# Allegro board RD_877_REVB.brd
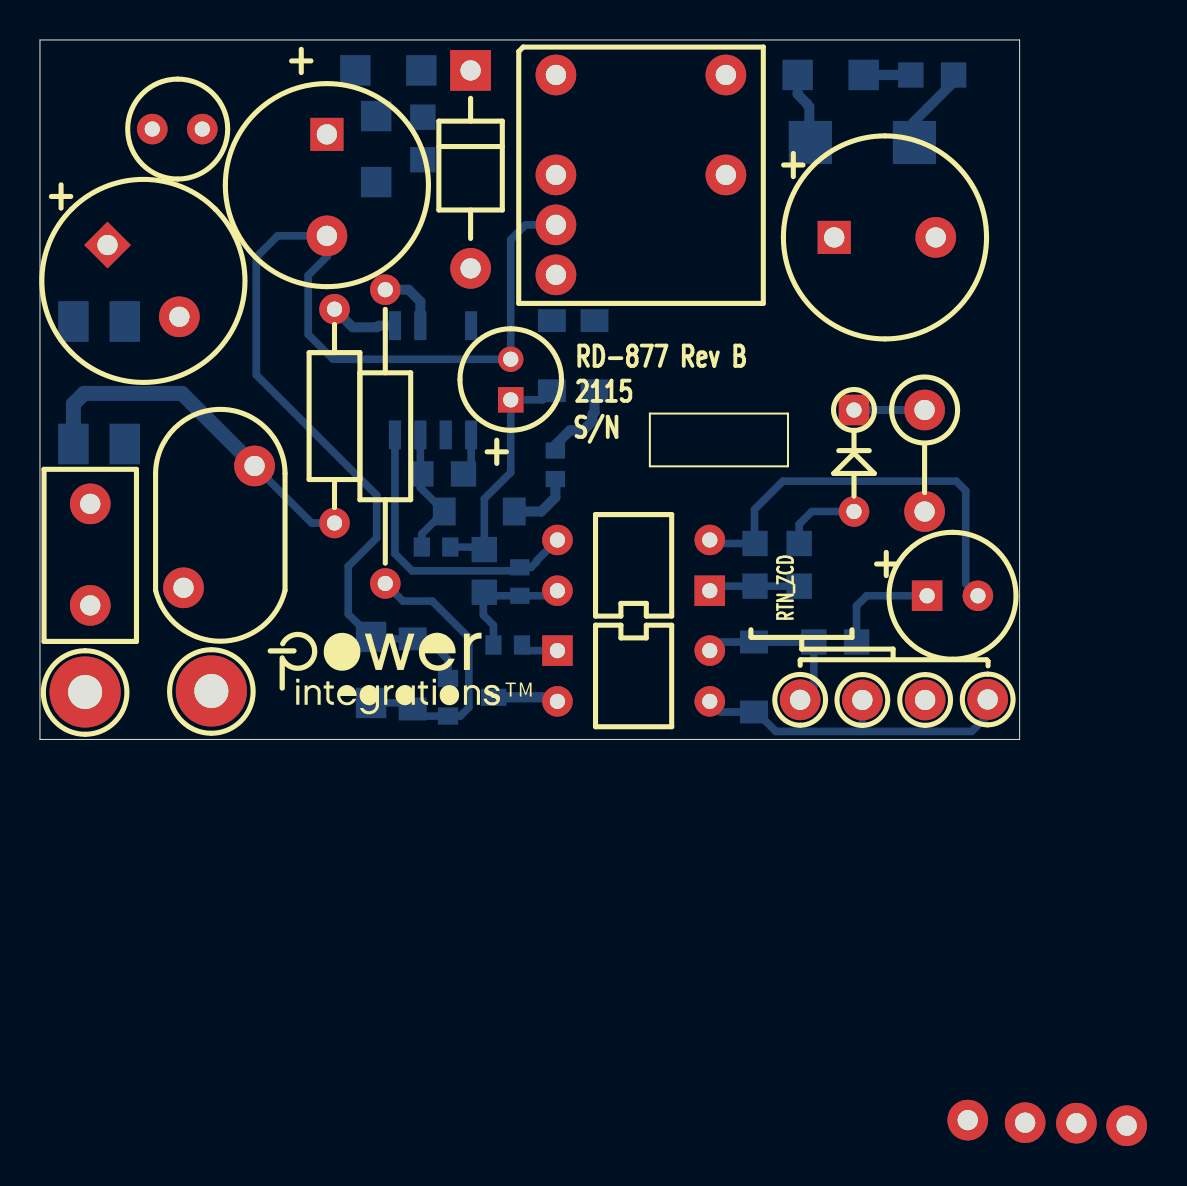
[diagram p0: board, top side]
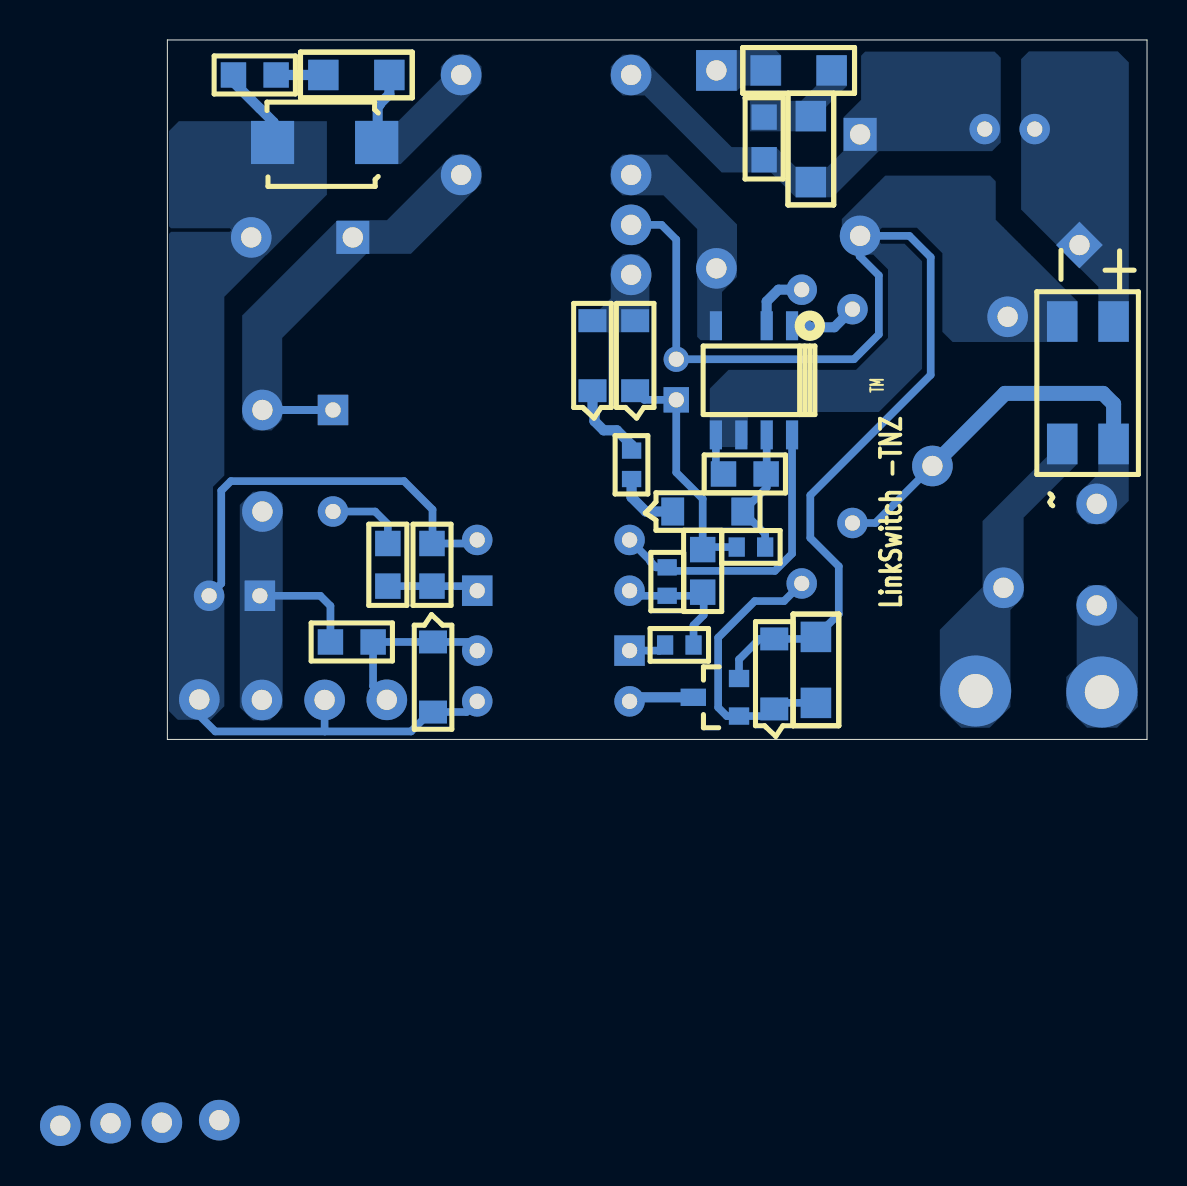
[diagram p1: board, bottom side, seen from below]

Outline 49 x 35 mm; copper layers: TOP, BOTTOM. Coordinates in mm from the lower left corner of the outline.
Outline path: 0,35 49,35 49,0 0,0 0,35

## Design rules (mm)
constraint set DEFAULT: min track width 0.508

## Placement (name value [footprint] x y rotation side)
BR1  B10S-G  [PISMSOIC4]  4.24 14.78 180 bottom
C1  6.8 uf  [PIPOLCAPCYLD400LS200040]  3.38 24.74 315 top
C2  10 uF  [PIPOLCAPCYLD400LS200040]  14.35 30.28 270 top
C3  2.2 nF  [PISMC0805]  19.15 29.01 90 bottom
C4  560 pF  [PISMC0805]  43.56 33.25 0 bottom
C5  680 uF  [PIPOLCAPCYLD400LS200040]  39.73 25.12 0 top
C6  220 uF  [PIPOLCAPCYLD250LS100030]  44.37 7.19 0 top
C7  10 uF  [PIPOLCAPCLYD200LS80030]  23.55 16.99 90 top
C8  100 nF  [PISMC0805]  19.05 13.28 0 bottom
C9  1000 pF  [PISMC0603]  24 7.19 90 bottom
D1  SS2H10-E3/52T  [PISMSMB]  38.53 29.87 0 bottom
D2  1N4007  [PIDV200X110X040DO41]  21.54 33.48 270 top
D3  1N4148W RHG  [PI_SM_SOD-123_12]  25.6 17.45 90 bottom
D4  1N4148W RHG  [PI_SM_SOD-123_12]  27.74 17.45 90 bottom
F1  1 A  [PI_RST_MICROFUSE]  2.51 6.71 90 top
L  WHT  [PITPKEYSTONE125X125]  2.26 2.37 0 top
L1  1000 uH  [PICHOKETOKINVD216H413LS098D030]  5.62 30.54 0 top
L2  Ferrite Bead  [PI12WRESD180LS675D040]  44.25 16.48 270 top
N  BLK  [PITPKEYSTONE125X125]  8.57 2.42 0 top
NOREF  -  []  -150.78 54.23 0 top
NOREF#2  -  []  -228.6 -144.78 0 top
NOREF#3  -  []  49 0 90 top
NOREF#4  -  []  0 35 0 top
NOREF#5  -  []  11.4 5.82 0 top
Q1  2N7002  [PISMSOT23123_1]  20.41 3.05 90 bottom
R2  120  [PISMR1206]  15.77 33.48 0 bottom
R3  100 k  [PISMR1206]  16.81 27.89 90 bottom
R4  100  [PISMR1206]  41.2 33.25 180 bottom
R5  392  [PISMR0805]  37.97 9.8 270 bottom
R6  2.00 k  [PISMR0805]  35.76 7.67 90 bottom
R7  24 k  [PISMR0603]  19.1 9.63 0 bottom
R8  510 k  [PI14WVRESD100LS100D030#2]  14.73 9.83 90 top
R9  240 k  [PISMR1206]  16.56 5.13 270 bottom
R10  24 k  [PISMR0603]  22.68 4.72 0 bottom
R11  100 k  [PISMR0805]  40.84 4.88 180 bottom
R13  0.0  [PISMR0805]  22.23 7.37 90 bottom
R14  510 k  [PI14WVRESD100LS100D030]  17.27 7.8 90 top
R15  2.4  [PISMR0603]  25.78 14.45 270 bottom
RTN  BLK  [PITPKEYSTONE100X100]  47.4 2 0 top
RTN_ZCD  BLK  [PITPKEYSTONE100X100]  41.13 1.97 0 top
RV1  300 Vac  [PIDISC350X225LS240X140040]  10.73 13.68 270 top
T1  EE13  [PI_BOBBIN_EE13V_10P]  25.81 33.25 270 top
U1  LNK3306  [PISMSO8_NOP3]  17.75 20.7 0 bottom
U2  PS2501-1-H-A  [PI_DIP4]  33.5 7.44 90 top
U3  LTV817D  [PI_DIP4]  25.88 4.45 270 top
UNK+12V  RED  [PITPKEYSTONE100X100]  44.27 1.97 0 top
VR2  BZX79-B11  [PIDV200X080X030DO35]  40.72 16.48 270 top
VR3  MMSZ4693T1G  [PI_SM_SOD-123_12]  18.64 1.52 90 bottom
VR4  MMSZ4689T1G  [PI_SM_SOD-123_12]  35.71 4.88 270 bottom
VR5  MMSZ5234B-7-F  [PI_SM_SOD-123_12]  23.72 11.4 180 bottom
ZCD  BLUE  [PITPKEYSTONE100X100]  38.02 1.98 0 top

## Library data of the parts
BR1 = DIODE BRIDGE_~~+-: alternate symbols: (pi_sm_soic4_slot)
C1 C6 = CAP POL
C2 C5 = CAP POL: alternate symbols: (pipolcapclyd395x630ls200030h)
C3 C4 C8 C9 = CAP NP
C7 = CAP POL: alternate symbols: (pipolcapclyd200ls80030h)
D1 = DIODE SCHOTTKY
D2 = DIODE: alternate symbols: (pidax475x125040do41,pidv200x110x040do41wbead,pidax390x125040do41)
D3 D4 = DIODE: alternate symbols: (pi_sm_sod-123_12_1)
F1 = FUSE: alternate symbols: (pirstmicrofusehoz)
L N RTN RTN_ZCD UNK+12V ZCD = TESTPOINT
L1 = INDUCTOR
L2 = INDUCTOR: alternate symbols: (pi12wvresd180ls150d040,pi12wvresd180ls200d040,pi12wvresd180ls250d040)
Q1 = FET_N_GSD
R2-R7 R9-R11 R15 = R
R8 R14 = R: alternate symbols: (pi14wvresd100ls125d030,pi14wvresd100ls150d030,pi14wvresd100ls200d030,pi14wvresd100ls300d030,pi14wresd100ls400d030,pi14wresd100ls500d030)
R13 = R: alternate symbols: (pismr0805_1)
RV1 = VARISTOR
T1 = BEE13/10PINS/GENERIC
U1 = LNK-TNZ
U2 U3 = OPTO_A_B
VR2 = DIODE_ZENER: alternate symbols: (pidax375x070030do35)
VR3-VR5 = DIODE_ZENER

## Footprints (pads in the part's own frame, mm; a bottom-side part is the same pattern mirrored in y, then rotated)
PI12WRESD180LS675D040
  round 2.032 hole 1.016: 1(0,0) 2(5.08,0)
PI14WVRESD100LS100D030
  round 1.524 hole 0.762: 1(0,0) 2(14.7,0)
PI14WVRESD100LS100D030#2
  round 1.524 hole 0.762: 1(1,0) 2(11.7,0)
PI_BOBBIN_EE13V_10P
  round 2.032 hole 1.016: 1(0,0) 2(52.299,20.599) 3(5.001,0) 4(7.501,0) 5(10,0) 6(52.578,28.55) 7(52.451,26.035) 8(5.001,8.501) 9(52.426,23.47) 10(0,8.501)
PI_DIP4
  rect 1.524x1.524 hole 0.762: 1(0,0)
  round 1.524 hole 0.762: 2(2.54,0) 3(2.54,7.62) 4(0,7.62)
PI_RST_MICROFUSE
  round 2.032 hole 1.016: 1(0,0) 2(5.08,0)
PI_SM_SOD-123_12
  rect 1.143x1.397 smd: 1(0,0) 2(3.505,0)
PICHOKETOKINVD216H413LS098D030
  round 1.524 hole 0.762: 1(0,0) 2(2.5,0)
PIDISC350X225LS240X140040
  round 2.032 hole 1.016: 1(0,0) 2(6.096,-3.556)
PIDV200X080X030DO35
  rect 1.524x1.524 hole 0.762: 1(0,0)
  round 1.524 hole 0.762: 2(5.08,0)
PIDV200X110X040DO41
  rect 2.032x2.032 hole 1.016: 1(0,0)
  round 2.032 hole 1.016: 2(9.906,0)
PIPOLCAPCLYD200LS80030
  rect 1.27x1.27 hole 0.762: 1(0,0)
  round 1.27 hole 0.762: 2(2.032,0)
PIPOLCAPCYLD250LS100030
  rect 1.524x1.524 hole 0.762: 1(0,0)
  round 1.524 hole 0.762: 2(2.54,0)
PIPOLCAPCYLD400LS200040
  rect 1.651x1.651 hole 1.016: 1(0,0)
  round 2.032 hole 1.016: 2(5.08,0)
PISMC0603
  rect 0.813x0.965 smd: 1(0,0) 2(1.422,0)
PISMC0805
  rect 1.27x1.27 smd: 1(0,0) 2(2.134,0)
PISMR0603
  rect 0.813x0.965 smd: 1(0,0) 2(1.422,0)
PISMR0805
  rect 1.27x1.27 smd: 1(0,0) 2(2.134,0)
PISMR1206
  rect 1.524x1.524 smd: 1(0,0) 2(3.302,0)
PISMSMB
  rect 2.159x2.159 smd: 1(0,0) 2(5.207,0)
PISMSO8_NOP3
  rect 0.61x1.448 smd: 1(0,0) 2(1.27,0) 4(3.81,0) 5(3.81,5.461) 6(2.54,5.461) 7(1.27,5.461) 8(0,5.461)
PISMSOIC4
  rect 1.524x2.032 smd: 1(0,0) 2(2.571,0) 3(2.571,6.129) 4(0,6.129)
PISMSOT23123_1
  rect 0.864x1.016 smd: 1(-1.88,0) 2(0,0)
  rect 0.864x1.27 smd: 3(-0.94,2.286)
PITPKEYSTONE100X100
  round 2.032 hole 1.016: 1(0,0)
PITPKEYSTONE125X125
  round 3.556 hole 1.702: 1(0,0)

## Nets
BIAS: D3.2 D4.2 T1.5
BP: C8.1 R7.1 U1.7 VR5.2
N4253666: C4.1 R4.1
N4253670: C4.2 C5.2 C6.2 D1.2 R6.2 RTN.1 RTN_ZCD.1 U2.2 U3.3(E) VR4.2
N4254079: BR1.4 C1.2 C2.2 C7.2 C8.2 Q1.2(S) R9.1 T1.4 U1.5 U1.6 VR3.2
N4254091: C7.1 D3.1 R7.2 R13.2
N4254098: C2.1 C3.1 L1.2 R3.1 T1.1
N4254129: C3.2 R2.1 R3.2
N4254146: D2.1 R2.2
N4254163: D2.2 T1.3 U1.4
N4254668: C9.2 U1.8 U2.3(E)
N4254798: R5.1 VR2.2
N4254829: R5.2 R6.1 U2.1
N4255085: BR1.3 C1.1 L1.1
N4255357: BR1.2 F1.2 R8.1 RV1.1
N4255389: F1.1 L.1
N4255403: BR1.1 N.1 RV1.2
N4255537: R8.2 U1.1
N4259135: Q1.1 R9.2 R14.1 VR3.1
N4259502: R10.2 U3.1
N4259699: R11.2 U3.4 VR4.1 ZCD.1
N4266456: C9.1 R10.1 R13.1 U2.4
N4272601: D1.1 R4.2 T1.10
N4274175: C5.1 L2.1 T1.8 VR2.1
N4274624: C6.1 L2.2 R11.1 UNK+12V.1
N4282141: R14.2 U1.2
N4296647: D4.1 R15.1
N4296671: R15.2 VR5.1
N42589121: Q1.3 U3.2

Pads without a net: T1 2 6 7 9

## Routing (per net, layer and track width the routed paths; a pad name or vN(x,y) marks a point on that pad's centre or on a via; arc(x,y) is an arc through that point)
BP: length 6.6
  BOTTOM w0.381: R7.1 19.1,10.29 VR5.2 19.02,12.6 19.02,13.26 C8.1 19.02,13.31 U1.7
N4253666: length 2.4
  BOTTOM w0.508: R4.1 C4.1
N4253670: length 42.1
  BOTTOM w0.381: C6.2 46.3,7.8 46.3,12.45 45.82,12.93 37.16,12.93 35.74,11.5 35.74,9.83 R6.2 33.68,9.8 U2.2 ; 41.12,0.4 41.13,0.41 RTN_ZCD.1 ; 41.12,0.4 46.6,0.4 47.4,1.2 RTN.1 ; 41.12,0.4 36.81,0.4 35.84,1.37 VR4.2 34.04,1.37 33.5,1.91
  BOTTOM w0.5: 44.39,31.58 43.69,30.89 43.69,30.07
  BOTTOM w0.508: C4.2 45.69,32.89 44.39,31.58
N4254079: length 58.4
  BOTTOM w0.381: 21.56,13.67 21.56,13.64 ; 21.56,13.67 U1.5 ; 21.56,13.67 C8.2 ; T1.4 24.28,25.75 23.55,25.01 C7.2 14.66,19.02 13.42,20.27 13.42,23.22 14.38,24.18 14.38,25.17 ; C2.2 11.89,25.2 10.82,24.13 10.82,18.24 16.84,12.22 16.84,10.08 15.42,8.66 15.42,6.27 R9.1 16.66,5.03 VR3.2 19.38,5.03 20.41,4 Q1.2
N4254091: length 12
  BOTTOM w0.381: R7.2 22.1,9.63 R13.2 22.23,12.04 23.55,13.36 C7.1 25.15,16.99 D3.1
N4254668: length 15.1
  BOTTOM w0.381: U2.3 24.84,8.94 24.84,8.89 24.56,8.61 C9.2 23.83,8.43 18.62,8.43 17.75,9.29 U1.8
N4254798: length 4
  BOTTOM w0.381: R5.1 37.97,10.77 38.61,11.4 VR2.2
N4254829: length 4.6
  BOTTOM w0.381: U2.1 33.73,7.67 R6.1 R5.2
N4255357: length 18
  BOTTOM w0.381: RV1.1 13.59,10.83 R8.1
  BOTTOM w0.75: BR1.2 1.67,16.78 2.2,17.31 7.1,17.31 RV1.1
  BOTTOM w1: 2.49,11.84 2.51,11.81 F1.2
N4255403: length 0.1
  BOTTOM w1: 9.02,2.54 8.98,2.5
N4255537: length 3.4
  BOTTOM w0.5: R8.2 15.64,20.62 16.87,20.62 16.95,20.7 U1.1
N4259135: length 14.1
  BOTTOM w0.381: R9.2 18.34,1.83 VR3.1 19,1.17 Q1.1 21.02,1.17 21.45,1.6 21.45,5.09 19.62,6.92 18.15,6.92 R14.1
N4259502: length 1.9
  BOTTOM w0.381: R10.2 24.38,4.45 U3.1
N4259699: length 8.6
  BOTTOM w0.381: 33.5,4.45 33.93,4.88 VR4.1 R11.2 38.71,2.67 ZCD.1
N4266456: length 6.7
  BOTTOM w0.381: R10.1 22.68,5.71 22.17,6.22 22.17,7.32 R13.1 22.4,7.19 C9.1 25.63,7.19 U2.4
N4272601: length 3.4
  BOTTOM w0.5: R4.2 37.9,32.28 38.38,31.8 38.38,31.76 38.48,31.66 38.48,30.07
N4274175: length 3.5
  BOTTOM w0.4: VR2.1 L2.1
N4274624: length 5.5
  BOTTOM w0.381: R11.1 40.84,6.68 41.35,7.19 C6.1
N4282141: length 3.2
  BOTTOM w0.5: U1.2 19.02,21.92 18.44,22.5 R14.2
N4296647: length 4.2
  BOTTOM w0.508: D4.1 27.74,16.37 27.64,16.27 27.64,15.93 27.18,15.47 26.52,15.47 25.78,14.73 R15.1
N4296671: length 3.3
  BOTTOM w0.508: VR5.1 25.07,11.4 25.78,12.12 R15.2
N42589121: length 3.3
  BOTTOM w0.508: 25.88,1.91 25.68,2.11 Q1.3

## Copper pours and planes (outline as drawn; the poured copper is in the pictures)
BIAS on BOTTOM: 24.89,23.77 24.89,20.37 28.42,20.37 28.45,20.4 28.45,21.54 27.36,21.54 26.82,22.07 26.82,23.67 26.21,24.28 25.4,24.28
N4253670 on BOTTOM: 48.92,30.44 48.92,25.68 48.82,25.58 45.87,25.58 45.82,25.52 45.82,25.47 45.88,25.4 48.82,25.4 48.92,25.3 48.92,1.42 48.48,0.98 47.95,0.98 47.95,0.98 46.83,0.98 46.15,1.66 46.15,7.14 46.72,7.71 46.72,12.64 46.15,13.21 46.15,22.15 44.07,24.23 44.04,24.23 41.02,27.25 41.02,30.93 48.43,30.93
N4254079 on BOTTOM: 21.87,14.68 21.87,17.55 20.93,18.49 14.55,18.49 12.95,20.09 12.95,23.52 13.69,24.26 14.76,24.26 15.27,24.77 15.27,26.04 13.09,28.21 7.85,28.21 7.57,27.93 7.57,26.01 3.48,21.92 3.48,19.89 9.73,19.89 10.24,20.4 10.24,24.33 11.51,25.6 13.26,25.6 13.41,25.45 13.41,24.92 13.3,24.8 12.13,24.8 11.25,23.93 11.25,18.54 13.41,16.38 19.68,16.38 19.96,16.1 19.96,14.73 20.07,14.63 21.82,14.63
N4254098 on BOTTOM: 7.62,34.42 14.1,34.42 14.3,34.21 14.3,32 15.17,31.13 15.17,29.45 15.98,28.65 17.57,28.65 18.56,29.64 20.78,29.64 23.38,32.25 23.38,32.25 25.4,34.27 26.23,34.27 26.82,33.67 26.82,32.82 26.22,32.22 25.13,32.22 24.99,32.09 22.53,29.63 21.27,28.37 18.97,28.37 18.97,28.37 18.81,28.37 17.57,27.13 15.72,27.13 13.41,29.44 7.75,29.44 7.32,29.87 7.32,34.11
N4254129 on BOTTOM: 16.05,31.65 16.05,30.43 19.86,30.43 19.86,31.95 17.3,31.95 16.54,32.72 16.54,34.21 16.51,34.24 15.09,34.24 15.01,34.16 15.01,32.69
N4254146 on BOTTOM: 22.56,32.46 20.5,32.46 20.24,32.72 18.29,32.72 18.29,34.21 18.57,34.49 22.48,34.49 22.56,34.42
N4254163 on BOTTOM: 24,29.26 26.24,29.26 26.83,28.68 26.83,27.81 26.24,27.23 24.19,27.23 22.5,25.54 22.5,20.15 22.33,19.98 21.26,19.98 21.26,22.39 20.51,23.14 20.51,25.77
N4255085 on BOTTOM: 0.91,33.88 1.46,34.43 5.91,34.43 6.3,34.04 6.3,26.52 2.43,22.65 2.43,19.9 2.43,19.9 0.91,19.9
N4255357 on BOTTOM: 3.53,12.19 2.44,13.28 2.44,15.8 0.91,15.8 0.91,11.94 2.08,10.77 2.95,10.77 3.53,11.35
N4255389 on BOTTOM: 0.46,1.63 1.5,0.58 3,0.58 4.04,1.63 4.04,3.12 3.52,3.64 3.52,7.12 2.92,7.72 2.08,7.72 0.46,6.1
N4255403 on BOTTOM: 6.17,11.1 6.17,7.14 6.83,6.48 6.83,1.63 7.87,0.58 9.3,0.58 10.36,1.65 10.36,5.49 8.23,7.62 8.23,10.92 5,14.15 5,15.8 3.48,15.8 3.48,13.79
N4272601 on BOTTOM: 33.88,34.27 34.72,34.27 35.32,33.67 35.32,33.07 37.44,30.95 39.61,30.95 39.61,28.79 37.32,28.79 33.29,32.83 33.29,33.67
N4274175 on BOTTOM: 45.26,21.21 45.26,16.02 44.69,15.46 43.79,15.46 43.26,15.99 43.26,20.09 39.05,24.3 36.82,24.3 33.29,27.83 33.29,28.66 33.89,29.26 34.74,29.26 38.02,25.98 40.49,25.98
N4274624 on BOTTOM: 43.23,11.81 43.23,1.6 43.87,0.96 44.72,0.96 45.38,1.61 45.38,11.73 44.72,12.39 44.72,12.4 43.82,12.4

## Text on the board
Ref Des/Silkscreen Bottom: TM | LinkSwitch -TNZ
Ref Des/Silkscreen Top: RTN_ZCD | S/N | 2115 | RD-877 Rev B
User.5: 14.  FAB HOUSE LOGO,DATE CODE TO BE IN SILK SCREEN ONLY.DO NOT USE COPPER. | 13.  MATERIAL FR4 COPPER 2oz THICKNESS 0.062" | PLEASE DELETE THESE PINS
User.8: FIGURE | FINISHED_SIZE | 30.0 | 40.0 | 67.0 | DRILL CHART: TOP to BOTTOM | ALL UNITS ARE IN MILS | PLATED | QTY | 20 | 28 | 2
